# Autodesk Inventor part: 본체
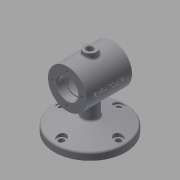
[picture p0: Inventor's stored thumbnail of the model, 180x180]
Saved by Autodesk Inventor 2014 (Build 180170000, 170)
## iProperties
Created: 2018-12
Part Number: 본체
Material: Generic
Document SubType Name: Modeling
Designer: kh
Density: 1 g/cm^3
Appearance: Default
Author: kh
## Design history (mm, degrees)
sketch "Sketch1"
  geometry: C1 r 55 at (0, 0); 1 further point
  constraints: 1 centre point, 1 coincident
  dimensions: "d0" = 110 diameter of C1
extrude "Extrusion1" new body sketch "Sketch1" distance "d1" = 11; taper "d2" = 0 deg
sketch "Sketch2"
  geometry: L1 (0, 0)-(0, 75); L2 (-55, 0)-(55, 0) reference; C1 r 30 at (0, 75)
  constraints: 2 end point, 1 centre point, 1 vertical
  dimensions: "d3" = 60 diameter of C1; "d4" = 75 distance from line of L1.end L2
extrude "Extrusion2" join sketch "Sketch2" stored distance "d5" = 70; taper "d6" = 0 deg
sketch "Sketch3"
  geometry: C1 r 30 at (0, 0) reference; C2 r 16 at (0, 0); 1 further point
  constraints: 1 centre point, 1 coincident
  dimensions: "d7" = 32 diameter of C2
extrude "Extrusion3" cut sketch "Sketch3" distance "d8" = 12; taper "d9" = 0 deg
sketch "Sketch4"
  geometry: C1 r 16 at (0, 0) reference; C2 r 14 at (0, 0); 1 further point
  constraints: 1 centre point, 1 coincident
  dimensions: "d10" = 28 diameter of C2
extrude "Extrusion4" cut sketch "Sketch4" distance "d11" = 3; taper "d12" = 0 deg
sketch "Sketch6"
  geometry: C1 r 30 at (0, 75) reference; C2 r 25 at (0, 75); 1 further point
  constraints: 1 centre point, 1 coincident
  dimensions: "d13" = 50 diameter of C2
extrude "Extrusion5" cut sketch "Sketch6" stored distance "d14" = 40; taper "d15" = 0 deg
sketch "Sketch7"
  geometry: C1 r 30 at (0, 0) reference; C2 r 16 at (0, 0); 1 further point
  constraints: 1 centre point, 1 coincident
  dimensions: "d16" = 32 diameter of C2
extrude "Extrusion6" cut sketch "Sketch7" distance "d17" = 12; taper "d18" = 0 deg
sketch "Sketch8"
  geometry: C1 r 16 at (0, 0) reference; C2 r 14 at (0, 0); 1 further point
  constraints: 1 centre point, 1 coincident
  dimensions: "d19" = 28 diameter of C2
extrude "Extrusion7" cut sketch "Sketch8" distance "d20" = 3; taper "d21" = 0 deg
sketch "Sketch9"
  geometry: L1 (0, 23)-(0, -23); L2 (-23, 0)-(23, 0); C1 r 30 at (0, 0) reference; A1 r 23 centre (0, 0) between (0, 23) and (0, -23); 6 further points
  constraints: 5 coincident, 4 end point, 4 point on circle, 2 midpoint, 1 centre point, 1 perpendicular, 1 vertical
  dimensions: "d22" = 46 diameter of A1
hole "Hole1" sketch "Sketch9" at (0, 23), (23, 0), (0, -23), (-23, 0) diameter "d23" = 3.459; stored, may be unused: countersink angle "d27" = 90 deg, drill point angle "d29" = 118 deg; dims "d24" = 8, "d25" = 4, "d26" = 2, "d28" = 10
mirror "Mirror1"
sketch "Sketch10"
  geometry: C1 r 55 at (0, 0) reference; C2 r 12 at (0, 0); 1 further point
  constraints: 1 centre point, 1 coincident
  dimensions: "d30" = 24 diameter of C2
extrude "Extrusion8" join sketch "Sketch10" stored distance "d31" = 3; taper "d32" = 0 deg
workplane "Work Plane1"
sketch "Sketch11"
  geometry: C1 r 55 at (0, 0) reference; C2 r 10 at (0, 0); 1 further point
  constraints: 1 centre point, 1 coincident
  dimensions: "d34" = 20 diameter of C2
extrude "Extrusion9" join sketch "Sketch11" stored distance "d35" = 3; taper "d36" = 0 deg
sketch "Sketch12"
  geometry: C1 r 10 at (0, 0) reference; C2 r 5 at (0, 0); 1 further point
  constraints: 1 centre point, 1 coincident
  dimensions: "d37" = 10 diameter of C2
extrude "Extrusion10" cut sketch "Sketch12" stored distance "d38" = 3; taper "d39" = 0 deg
chamfer "Chamfer1" distance "d40" = 1; stored, may be unused: second distance "d41" = 2, angle "d42" = 45 deg
sketch "Sketch14"
  geometry: L1 (55, 11)-(-55, 11) reference; L2 (55, 0)-(55, 11) reference; L3 (0, 0)-(0, 22.157); L4 (12, 11)-(12, 45) reference; L5 (55, 11)-(12, 22.522); L6 (12, 11)-(12, 22.522); L7 (12, 11)-(55, 11)
  constraints: 8 end point, 2 collinear, 1 parallel, 1 point on line
  dimensions: "d43" = 75 deg angle of L5 L2
revolve "Revolution1" sketch "Sketch14" stored, may be unused: angle "d44" = 90 deg
workplane "Work Plane2"
sketch "Sketch15"
  geometry: L1 (-24.887, 85.448)-(24.887, 85.448); L2 (24.887, 85.448)-(24.887, 64.552); L3 (24.887, 64.552)-(-24.887, 64.552); L4 (-24.887, 64.552)-(-24.887, 85.448); L5 (-24.887, 75)-(24.887, 75); L6 (0, 64.552)-(0, 85.448); L7 (-35, 105)-(-35, 45) reference; 1 further point
  constraints: 4 end point, 4 midpoint, 2 other
  dimensions: "d46" = 35 distance from line of L6.end L7; "d47" = 30 vertical distance of L5.start L7.start
emboss "Emboss1" sketch "Sketch15" dims "d1" = 11, "d2" = 0, "d48" = 0.5, "d49" = 0
fillet "Fillet1" dims "d50" = 3
chamfer "Chamfer2" distance "d51" = 1; stored, may be unused: second distance "d52" = 2, angle "d53" = 45 deg
fillet "Fillet2" dims "d54" = 0.3
fillet "Fillet3" dims "d55" = 3
sketch "Sketch17"
  geometry: L1 (0, 44)-(0, -44); L2 (-44, 0)-(44, 0); C1 r 55 at (0, 0) reference; C2 r 4.5 at (0, 44); C3 r 4.5 at (-44, 0); C4 r 4.5 at (44, 0); C5 r 4.5 at (0, -44); A1 r 44 centre (0, 0) between (0, 44) and (0, -44); 2 further points
  constraints: 5 centre point, 5 coincident, 4 end point, 4 point on circle, 2 midpoint, 1 perpendicular, 1 vertical
  dimensions: "d58" = 88 diameter of A1; "d59" = 9 diameter of C2; "d60" = 9 diameter of C3; "d61" = 9 diameter of C4; "d62" = 9 diameter of C5
extrude "Extrusion11" cut sketch "Sketch17" distance "d63" = 10; taper "d64" = 0 deg
sketch "Sketch18" dims "d11" = 3
  geometry: C1 r 4.5 at (0, 0) reference; C2 r 7 at (0, 0); 1 further point
  constraints: 1 centre point, 1 coincident
  dimensions: "d66" = 14 diameter of C2
extrude "Extrusion12" cut sketch "Sketch18" stored distance "d67" = 10; taper "d68" = 0 deg
pattern_circular "Circular Pattern1" dims angle "d70" = 360 deg
body "Solid1"
other parameters: "d33" = 112
